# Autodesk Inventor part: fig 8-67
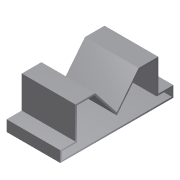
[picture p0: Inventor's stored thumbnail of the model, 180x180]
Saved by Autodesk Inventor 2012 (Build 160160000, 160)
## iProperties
Shininess: 77.0
Length Units: 11269
Angle Units: 11279
Time Units: 11290
Mass Units: 11283
Length Display Precision: 3
Angle Display Precision: 2
Created: 2002-01
Part Number: fig 8-67
Document SubType Name: Modeling
Designer: ***
Density: 1 g/cm^3
Material: Default
Density: 0.0
Volumn: 0.0
Area: 0.0
PropertySet Name: Model Information
Control State: 0
Master: False
Checked Out: False
Author: ***
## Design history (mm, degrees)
node "Sketch1"
sketch "Sketch2"
  geometry: L1 (0, 0)-(-14.184, 17.961); L2 (-14.184, 17.961)-(-26.987, 17.961); L3 (-26.987, 17.961)-(-26.987, -2.947); L4 (-26.987, -2.947)-(-36.842, -2.947); L5 (-36.842, -2.947)-(-36.842, -10.132); L6 (26.987, 17.961)-(26.987, -2.947); L7 (14.184, 17.961)-(26.987, 17.961); L8 (26.987, -2.947)-(36.842, -2.947); L9 (36.842, -10.132)-(-36.842, -10.132); L10 (36.842, -2.947)-(36.842, -10.132); L11 (0, 0)-(14.184, 17.961)
  constraints: 22 end point, 2 horizontal, 2 parallel, 1 perpendicular
extrude "Extrusion1" new body sketch "Sketch2" distance "d0" = 35; taper "d1" = 0 deg
shell "Shell3" dims "d13" = 1
body "Solid1"
